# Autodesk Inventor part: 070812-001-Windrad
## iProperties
Shininess: 64.0
Length Units: 11269
Angle Units: 11279
Time Units: 11290
Mass Units: 11283
Length Display Precision: 3
Angle Display Precision: 2
Compacted: True
Part Number: 070812-001-Windrad
Document SubType Name: Modeling
Created: 2007-08
Material: Standard
Designer: mp
Density: 0.0
Volumn: 0.0
Area: 0.0
PropertySet Name: Model Information
Control State: 0
Master: False
Checked Out: False
Author: mp
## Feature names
1. Extrusion1
2. Extrusion2
3. Erhebung1
4. Bohrung1 [Hole]
5. Runde Anordnung1 [Circular Pattern]
